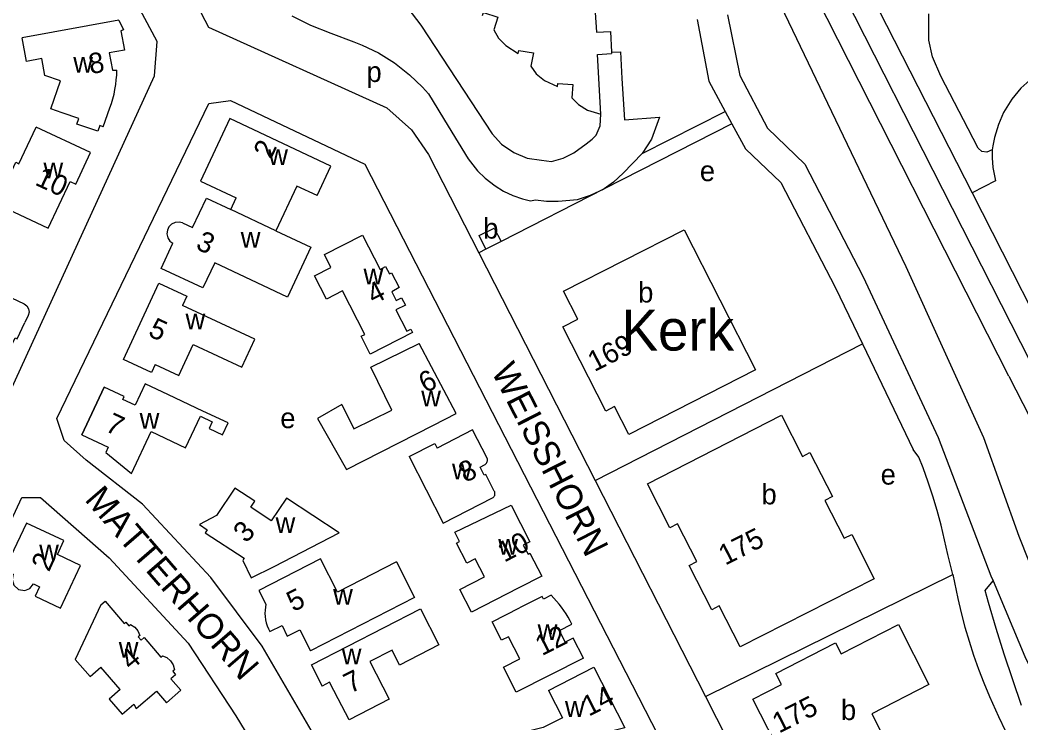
# Model space of a CAD drawing. Extents: x 158848 to 160613, y 385889 to 387762.
# Drawn here: x 159449.2 to 159645, y 386787.3 to 386924.8 of the extents above; entities that cross this region are included whole.
import ezdxf

# ---------------------------------------------------------------- set-up
doc = ezdxf.new("R2010")
doc.units = 0
for name, color, linetype in [('BLT_Basislijn', 7, 'Continuous'), ('BLT_Bebouwing', 7, 'Continuous'), ('BLT_Bebouwing_beschrifting', 7, 'Continuous'), ('BLT_Centroide', 7, 'Continuous'), ('BLT_Huisnummer', 7, 'Continuous'), ('BLT_Huisnummer_reeks', 7, 'Continuous'), ('BLT_Onderverdeling_panden', 7, 'Continuous'), ('BLT_Straatnaam', 7, 'Continuous')]:
    doc.layers.add(name, color=color, linetype=linetype)

msp = doc.modelspace()

# ---------------------------------------------------------------- linework, layer by layer
at = {"layer": 'BLT_Basislijn'}
for p, q in [((159642.66, 386855.15), (159599.65, 386939.76)), ((159593.58, 386936.96), (159622.47, 386876.62)), ((159648.81, 386854.1), (159607.24, 386935.86)), ((159626.97, 386920.9), (159627, 386926.08)), ((159627.69, 386917.65), (159626.97, 386920.9)), ((159629.31, 386913.82), (159627.69, 386917.65)), ((159634.66, 386903.55), (159629.31, 386913.82)), ((159647.35, 386913.56), (159645.02, 386911.51)), ((159645.02, 386911.51), (159643.23, 386909.32)), ((159486.14, 386908.53), (159490.34, 386909.11)), ((159643.23, 386909.32), (159641.6, 386906.73)), ((159456.36, 386846.86), (159486.14, 386908.53)), ((159641.6, 386906.73), (159640.59, 386904.4)), ((159588.47, 386904.54), (159563.46, 386891.77)), ((159636.63, 386899.79), (159634.66, 386903.55)), ((159640.59, 386904.4), (159639.84, 386901.84)), ((159639.84, 386901.84), (159639.54, 386900.23)), ((159637.38, 386899.14), (159636.63, 386899.79)), ((159638.32, 386898.99), (159637.38, 386899.14)), ((159639.39, 386899.44), (159638.32, 386898.99)), ((159639.54, 386900.23), (159639.39, 386899.44)), ((159602.75, 386896.61), (159614.14, 386874.61)), ((159563.46, 386891.77), (159543.28, 386881.47)), ((159540.34, 386879.98), (159538.94, 386879.26)), ((159608.68, 386872.59), (159614.01, 386861.47)), ((159561.67, 386834.72), (159614.01, 386861.47)), ((159614.01, 386861.47), (159623.91, 386840.81)), ((159642.66, 386855.15), (159675.21, 386790.95)), ((159457.8, 386842.55), (159456.36, 386846.86)), ((159462.11, 386838.72), (159457.8, 386842.55)), ((159625.04, 386839.31), (159623.91, 386840.81)), ((159473.11, 386830.1), (159462.11, 386838.72)), ((159486.51, 386815.74), (159473.11, 386830.1)), ((159496.56, 386802.33), (159486.51, 386815.74)), ((159583.26, 386792.43), (159631.71, 386816.34)), ((159637.99, 386813.18), (159639.56, 386815.1)), ((159506.61, 386785.09), (159496.56, 386802.33)), ((159640.63, 386788.54), (159647.72, 386773.62))]:
    msp.add_line(p, q, dxfattribs=at)
for points in [[(159378.73, 386868.21), (159381.51, 386870.25), (159384.89, 386871.94), (159390.8, 386873.2), (159397.02, 386873.2), (159403.72, 386871.28), (159415.21, 386866.02), (159440.57, 386853.09), (159443.92, 386851.65), (159447.27, 386852.13), (159475.51, 386913.9), (159475.98, 386920.61), (159471.2, 386929.7), (159460.12, 386951.5)], [(159608.45, 386947.37), (159609.58, 386941.77), (159635.45, 386891)], [(159477.85, 386939.23), (159486.03, 386923.44), (159520.96, 386907.65), (159525.75, 386903.34), (159529.1, 386898.55), (159538.94, 386879.26)], [(159521.87, 386931.43), (159527.59, 386923.85), (159534.57, 386913.21), (159541.55, 386902.57), (159543.39, 386900.57), (159545.82, 386898.92), (159548.42, 386897.8), (159551.21, 386897.38), (159553.18, 386897.16), (159555.46, 386897.79), (159557.56, 386898.84), (159559.96, 386900.64), (159561.1, 386901.53), (159561.87, 386902.29), (159562.32, 386903.21), (159562.68, 386904.14), (159562.79, 386906.39)], [(159502.36, 386925.67), (159506.01, 386923.84), (159509.95, 386922.24), (159514.48, 386920.6), (159516.12, 386919.94), (159519.28, 386918.42), (159522.42, 386916.43), (159525.4, 386914.09), (159527.91, 386911.7), (159529.07, 386910.41), (159532.95, 386904.05), (159536.84, 386897.7), (159538.71, 386895.33), (159540.19, 386893.9), (159542.13, 386892.36), (159543.76, 386891.36), (159545.62, 386890.49), (159547.46, 386889.83), (159549.06, 386889.45), (159550.02, 386889.66), (159552.2, 386889.42), (159554.48, 386889.36), (159558.26, 386889.73), (159560.76, 386890.56), (159563.46, 386891.77)], [(159581.66, 386924.93), (159583.96, 386912.85), (159587.17, 386906.95)], [(159587.6, 386925.88), (159589.99, 386914), (159595.45, 386903.65), (159602.75, 386896.61)], [(159564.9, 386918.55), (159566.64, 386918.63), (159566.95, 386913.37)], [(159566.95, 386913.37), (159567.43, 386905.31), (159574.28, 386905.8), (159572.75, 386901.5), (159570.91, 386898.7)], [(159490.34, 386909.11), (159516.66, 386896.66), (159588.92, 386755.88)], [(159570.91, 386898.7), (159587.17, 386906.95)], [(159587.17, 386906.95), (159588.47, 386904.54)], [(159588.47, 386904.54), (159591.14, 386899.62), (159598.04, 386893.01), (159608.68, 386872.59)], [(159639.39, 386899.44), (159639.35, 386897.88), (159639.52, 386896), (159640.02, 386893.39), (159635.45, 386891)], [(159570.91, 386898.7), (159567.18, 386894.84), (159565.29, 386893.1), (159563.46, 386891.77)], [(159635.45, 386891), (159655, 386852.65)], [(159538.94, 386879.26), (159561.67, 386834.72)], [(159622.47, 386876.62), (159637.71, 386843.11), (159644.61, 386823.85), (159651.79, 386805.73), (159658.98, 386790.78)], [(159614.14, 386874.61), (159628.8, 386843.11), (159639.15, 386816.08), (159639.56, 386815.1)], [(159631.71, 386816.34), (159630.69, 386820.27), (159630.08, 386823.14), (159629.39, 386825.99), (159628.62, 386828.83), (159627.78, 386831.64), (159626.86, 386834.42), (159625.87, 386837.18), (159625.04, 386839.31)], [(159561.67, 386834.72), (159583.26, 386792.43)], [(159449.52, 386831.37), (159453.18, 386831.37), (159466.59, 386819.58), (159482.04, 386802.91), (159491.39, 386788.68), (159497.08, 386779.33), (159500.74, 386768.76), (159508.06, 386749.25), (159509.27, 386740.71), (159510.09, 386736.65), (159507.24, 386735.84), (159449.92, 386721.2), (159447.48, 386722.01), (159425.13, 386772.02), (159423.91, 386775.67), (159425.13, 386778.93), (159449.52, 386831.37)], [(159631.71, 386816.34), (159632.66, 386811.64), (159633.32, 386808.83), (159634.05, 386806.05), (159634.85, 386803.28), (159635.74, 386800.53), (159636.69, 386797.81), (159637.73, 386795.12), (159638.84, 386792.46), (159640.02, 386789.83), (159640.63, 386788.54)], [(159639.56, 386815.1), (159645.76, 386800.27), (159650.93, 386789.63)], [(159645.15, 386790.69), (159643.41, 386795.69), (159641.75, 386800.72), (159640.17, 386805.77), (159638.66, 386810.85), (159637.99, 386813.18)], [(159583.26, 386792.43), (159600.4, 386758.82), (159625.25, 386766.9)]]:
    msp.add_lwpolyline(points, dxfattribs=at)
at = {"layer": 'BLT_Bebouwing'}
for p, q in [((159485.63, 386889.98), (159490.39, 386887.75)), ((159490.39, 386887.75), (159491.45, 386890.02)), ((159555.53, 386871.75), (159579.12, 386883.79)), ((159579.12, 386883.79), (159593.1, 386856.36)), ((159543.28, 386881.47), (159540.34, 386879.98)), ((159558.33, 386866.27), (159555.53, 386871.75)), ((159555.4, 386864.79), (159558.33, 386866.27)), ((159563.81, 386848.32), (159555.4, 386864.79)), ((159593.1, 386856.36), (159568.29, 386843.72)), ((159565.5, 386849.19), (159563.81, 386848.32)), ((159568.29, 386843.72), (159565.5, 386849.19))]:
    msp.add_line(p, q, dxfattribs=at)
for points in [[(159539.66, 386925.74), (159539.86, 386926.3), (159542.65, 386925.42), (159541.85, 386922.93), (159542.76, 386921.31), (159544.21, 386919.83), (159546.62, 386918.3)], [(159561.71, 386926.31), (159561.93, 386922.45), (159564.68, 386922.59)], [(159468.53, 386924.81), (159449.59, 386921.34)], [(159468.53, 386924.81), (159469.41, 386922.92), (159468.92, 386922.73)], [(159468.92, 386922.73), (159469.58, 386918.96), (159466.6, 386918.39), (159467.25, 386915.01), (159468.1, 386915.01)], [(159564.68, 386922.59), (159564.9, 386918.55)], [(159457.44, 386906.67), (159455.17, 386907.46), (159457.08, 386912.95), (159454.04, 386913.97), (159453.43, 386917.3), (159450.43, 386916.75), (159449.59, 386921.34)], [(159546.62, 386918.3), (159546.76, 386918.89)], [(159546.76, 386918.89), (159549.61, 386918.4), (159549.1, 386915.82), (159550.19, 386914.3), (159551.81, 386913.03), (159554.32, 386911.86)], [(159564.9, 386918.55), (159564.91, 386918.28)], [(159562.79, 386906.39), (159562.17, 386918.09), (159564.91, 386918.28)], [(159465.45, 386903.93), (159466.75, 386907.63), (159467.06, 386908.52), (159467.33, 386909.42), (159467.56, 386910.34), (159467.75, 386911.26), (159467.9, 386912.2), (159468.01, 386913.13), (159468.08, 386914.07), (159468.1, 386915.01)], [(159554.32, 386911.86), (159554.37, 386912.44)], [(159554.37, 386912.44), (159557.34, 386912.25), (159557.15, 386909.63), (159558.42, 386908.28), (159560.21, 386907.2), (159562.79, 386906.39)], [(159465.45, 386903.93), (159464.77, 386904.18), (159464.39, 386903.06), (159460.3, 386904.47), (159460.68, 386905.57), (159457.44, 386906.67)], [(159507.29, 386890.48), (159510, 386896.23), (159490.21, 386905.54), (159484.47, 386893.3), (159491.45, 386890.02)], [(159444.53, 386888.85), (159454.69, 386884.08), (159458.97, 386893.24), (159460.11, 386892.7), (159462.96, 386898.88), (159452.32, 386903.88)], [(159444.53, 386888.85), (159448.36, 386897), (159448.96, 386896.72), (159452.32, 386903.88)], [(159507.29, 386890.48), (159503.31, 386892.35), (159499.21, 386883.6)], [(159480.99, 386885.14), (159482.93, 386884.21), (159485.63, 386889.98)], [(159480.99, 386885.14), (159480.3, 386885.31), (159479.53, 386885.23), (159478.82, 386884.89), (159478.3, 386884.36), (159478, 386883.73), (159477.91, 386882.99), (159478.08, 386882.23), (159478.51, 386881.58), (159479.07, 386881.15)], [(159499.21, 386883.6), (159506.06, 386880.37), (159501.49, 386870.61)], [(159540.34, 386879.98), (159538.99, 386882.64), (159541.92, 386884.13), (159543.28, 386881.47)], [(159476.76, 386876.18), (159479.08, 386881.15)], [(159508.71, 386878.93), (159516.19, 386882.75), (159519.64, 386876.01), (159520.71, 386876.57), (159521.43, 386875.18), (159521.88, 386875.39), (159523.38, 386872.47), (159521.9, 386871.62), (159522.76, 386869.92), (159523.83, 386870.49), (159524.58, 386869.06), (159522.69, 386868.09), (159524.82, 386863.94), (159525.65, 386864.34), (159525.96, 386863.7), (159517.68, 386859.47)], [(159435.05, 386868.82), (159436.17, 386871.22), (159436.38, 386871.12), (159440.76, 386880.35), (159447.54, 386877.14), (159444.93, 386871.63), (159449.96, 386869.27), (159450.49, 386868.88), (159450.83, 386868.31), (159450.93, 386867.67), (159450.77, 386867.01), (159450.14, 386865.66)], [(159501.49, 386870.61), (159487.26, 386877.32), (159484.96, 386872.44), (159476.76, 386876.18)], [(159517.68, 386859.47), (159515.89, 386862.95), (159516.62, 386863.32), (159512.25, 386871.84), (159509.13, 386870.24), (159506.81, 386874.78), (159510, 386876.42), (159508.71, 386878.93)], [(159475.63, 386857.44), (159474.89, 386855.85), (159469.4, 386858.42), (159476.33, 386873.36), (159480.86, 386871.24)], [(159480.86, 386871.24), (159481.82, 386870.78), (159480.97, 386868.97)], [(159435.05, 386868.82), (159432.94, 386864.29), (159437.53, 386862.15), (159437.1, 386861.22), (159445.64, 386857.25), (159448.19, 386862.66), (159448.64, 386862.45), (159450.14, 386865.66)], [(159475.63, 386857.44), (159480.26, 386855.29), (159483.07, 386861.33), (159492.54, 386856.92), (159495.09, 386862.4), (159480.97, 386868.97)], [(159521.91, 386848.49), (159517.79, 386856.88), (159527.29, 386861.55)], [(159530.04, 386845.55), (159534.49, 386847.83), (159527.29, 386861.55)], [(159478.19, 386851.51), (159473.67, 386853.64), (159471.69, 386849.45), (159469.3, 386850.55), (159469.56, 386851.16), (159465.65, 386852.98), (159461.25, 386843.68), (159466.42, 386841.25), (159465.93, 386840.22)], [(159461.25, 386843.68), (159465.65, 386852.98)], [(159470.97, 386836.07), (159474.83, 386844.29), (159481.57, 386841.12), (159484.46, 386847.28), (159486.78, 386846.19), (159486.15, 386844.87), (159488.76, 386843.64), (159489.88, 386846), (159484.95, 386848.32), (159478.19, 386851.51)], [(159512.16, 386849.58), (159507.35, 386846.83), (159513.06, 386836.86), (159530.04, 386845.55)], [(159512.16, 386849.58), (159514.49, 386844.84), (159521.91, 386848.49)], [(159540.57, 386839.06), (159537.73, 386844.61), (159530.78, 386841.07)], [(159525.32, 386839.42), (159530.33, 386841.96), (159530.78, 386841.07)], [(159465.93, 386840.22), (159470.97, 386836.07)], [(159525.32, 386839.42), (159531.98, 386826.38), (159541.59, 386831.3)], [(159540.03, 386837.78), (159540.19, 386837.87), (159540.32, 386837.97), (159540.43, 386838.1), (159540.53, 386838.24), (159540.59, 386838.41), (159540.63, 386838.58), (159540.64, 386838.75), (159540.61, 386838.91), (159540.57, 386839.06)], [(159541.97, 386832.66), (159540.31, 386835.92), (159540.01, 386835.77), (159539.19, 386837.35), (159540.03, 386837.78)], [(159491.18, 386833.25), (159487.63, 386827.87), (159484.27, 386826.09)], [(159511.62, 386824.48), (159501.28, 386831.29), (159498.33, 386826.82), (159494.3, 386829.48), (159495.09, 386830.68), (159491.18, 386833.25)], [(159541.59, 386831.3), (159541.73, 386831.39), (159541.85, 386831.51), (159541.96, 386831.65), (159542.04, 386831.81), (159542.08, 386831.99), (159542.1, 386832.17), (159542.08, 386832.35), (159542.04, 386832.51), (159541.97, 386832.66)], [(159534.23, 386824.63), (159545.24, 386829.92), (159548.89, 386822.73), (159547.63, 386822.09), (159548.56, 386820.29), (159548.94, 386820.49), (159551.24, 386816.03), (159546.79, 386813.74)], [(159457.07, 386809.73), (159461.02, 386818.09), (159456.49, 386820.22), (159457.76, 386822.98), (159450.43, 386826.4), (159446.09, 386817.2), (159447.84, 386816.38), (159447.61, 386815.36), (159447.95, 386814.23), (159448.88, 386813.4), (159450.09, 386813.21), (159451.1, 386813.6), (159451.81, 386814.51), (159453.01, 386813.94), (159452.13, 386812.06), (159457.07, 386809.73)], [(159484.27, 386826.09), (159485.79, 386825.09), (159485.39, 386824.47), (159493.03, 386819.52), (159492.74, 386819.04), (159494.41, 386815.69), (159498.88, 386817.92)], [(159498.88, 386817.92), (159511.62, 386824.48)], [(159535.21, 386813.38), (159540.04, 386815.84), (159538.23, 386819.39), (159536.59, 386818.55), (159534.59, 386822.48), (159535.17, 386822.78), (159534.23, 386824.63)], [(159507.94, 386819.4), (159495.92, 386813.19), (159497.28, 386810.55)], [(159522.84, 386818.78), (159526.33, 386811.8), (159505.98, 386801.41)], [(159522.84, 386818.78), (159511.27, 386812.87), (159507.94, 386819.4)], [(159546.79, 386813.74), (159537.48, 386808.96), (159535.21, 386813.38)], [(159464.98, 386810.41), (159465.83, 386811.13), (159469.54, 386806.74), (159469.85, 386806.99), (159470.45, 386806.28), (159470.8, 386806.56), (159471.62, 386806.04), (159472.24, 386805.32), (159472.63, 386804.42), (159472.31, 386804.12), (159472.85, 386803.47), (159473.47, 386804.01)], [(159553.08, 386812.29), (159551.61, 386811.53), (159551.36, 386812.02), (159546.9, 386809.78)], [(159557.15, 386806.58), (159556.79, 386807.27), (159556.4, 386807.95), (159556, 386808.62), (159555.56, 386809.27), (159555.11, 386809.91), (159554.63, 386810.53), (159554.14, 386811.13), (159553.62, 386811.72), (159553.08, 386812.29)], [(159464.98, 386810.41), (159459.98, 386799.71), (159462.86, 386796.34), (159464.99, 386798.17)], [(159497.28, 386810.55), (159497.17, 386809.95), (159497.11, 386809.34), (159497.09, 386808.72), (159497.13, 386808.09), (159497.22, 386807.47), (159497.35, 386806.86), (159497.54, 386806.27), (159497.77, 386805.7), (159498.04, 386805.15)], [(159521.39, 386791.91), (159513.55, 386787.88), (159511.41, 386792.01), (159509.73, 386795.23), (159508.3, 386794.5), (159506.17, 386798.65), (159527.53, 386809.61)], [(159527.53, 386809.61), (159531.13, 386802.54), (159523.44, 386798.61), (159521.97, 386801.5), (159517.62, 386799.28), (159521.39, 386791.91)], [(159541.52, 386807.08), (159546.9, 386809.78)], [(159546.27, 386793.27), (159543.75, 386798.16), (159546.96, 386799.82), (159544.72, 386804.14), (159543.39, 386803.46), (159541.52, 386807.08)], [(159498.04, 386805.15), (159500.43, 386806.34), (159501.45, 386804.29), (159503.89, 386805.51), (159505.98, 386801.41)], [(159559.39, 386799.96), (159557.39, 386803.88), (159555.86, 386803.08), (159554.71, 386805.34), (159557.15, 386806.58)], [(159592.58, 386791.95), (159598.18, 386794.82), (159597.07, 386796.96), (159608.74, 386802.93), (159609.83, 386800.8), (159621.04, 386806.53), (159627.02, 386794.82), (159615.83, 386789.09), (159620.35, 386780.19), (159608.68, 386774.21), (159604.15, 386783.13), (159598.49, 386780.33), (159592.58, 386791.95)], [(159473.47, 386804.01), (159476.7, 386800.16), (159477.02, 386800.44), (159477.91, 386800.05), (159478.64, 386799.43), (159479.13, 386798.63), (159479.38, 386797.68), (159479.06, 386797.38), (159479.61, 386796.72), (159478.68, 386795.93), (159480.62, 386793.66), (159477.8, 386791.24)], [(159559.39, 386799.96), (159546.27, 386793.27)], [(159468.74, 386793.79), (159464.99, 386798.17)], [(159506.17, 386798.65), (159508.3, 386794.5)], [(159552.59, 386793.65), (159561.42, 386798.18), (159567.48, 386786.35), (159562.82, 386785.14), (159563.69, 386781.79), (159558.85, 386780.54)], [(159468.74, 386793.79), (159466.61, 386791.96), (159469.15, 386788.99), (159471.43, 386790.95), (159471.88, 386790.12), (159475.85, 386793.52), (159477.8, 386791.24)], [(159552.59, 386793.65), (159555.32, 386788.3), (159551.53, 386786.38), (159546.11, 386784.99), (159547.71, 386778.76)]]:
    msp.add_lwpolyline(points, dxfattribs=at)
msp.add_lwpolyline([(159571.93, 386834.1), (159598.16, 386847.49), (159602.25, 386839.43), (159603.72, 386840.2), (159608.14, 386831.56), (159606.66, 386830.8), (159610.43, 386823.42), (159611.91, 386824.17), (159616.31, 386815.51), (159590.08, 386802.15), (159585.99, 386810.18), (159584.5, 386809.43), (159580.09, 386818.08), (159581.57, 386818.84), (159577.81, 386826.22), (159576.33, 386825.46)], close=True, dxfattribs=at)
at = {"layer": 'BLT_Onderverdeling_panden'}
msp.add_line((159499.21, 386883.6), (159490.39, 386887.75), dxfattribs=at)

# ---------------------------------------------------------------- texts
at = {"layer": 'BLT_Bebouwing_beschrifting'}
msp.add_text('Kerk', height=8, dxfattribs=at).set_placement((159566.87, 386860.16))
at = {"layer": 'BLT_Centroide'}
for s, p in [('w', (159459.58, 386914.55)), ('p', (159516.96, 386912.71)), ('w', (159497.73, 386896.47)), ('w', (159453.75, 386893.88)), ('e', (159582.19, 386893.31)), ('b', (159539.8, 386882.06)), ('w', (159492.35, 386880.28)), ('w', (159516.38, 386873.08)), ('b', (159570.12, 386869.55)), ('w', (159481.55, 386864.31)), ('w', (159527.66, 386849.22)), ('w', (159472.57, 386844.84)), ('e', (159500.09, 386844.96)), ('w', (159533.7, 386834.92)), ('e', (159617.56, 386833.92)), ('b', (159594.25, 386830.05)), ('w', (159499.17, 386824.47)), ('w', (159542.73, 386820.19)), ('w', (159452.91, 386819.12)), ('w', (159510.43, 386810.41)), ('w', (159550.45, 386803.48)), ('w', (159468.48, 386800.06)), ('w', (159512.12, 386798.75)), ('w', (159555.8, 386788.47)), ('b', (159609.8, 386787.83))]:
    msp.add_text(s, height=4, dxfattribs=at).set_placement(p)
at = {"layer": 'BLT_Huisnummer'}
for s, rotation, p in [('8', 9.9027, (159462.97, 386914.24)), ('2', 64.8544, (159498.27, 386897.43)), ('10', 334.9368, (159451.9, 386892.67)), ('3', 334.9187, (159483.34, 386880.15)), ('4', 27.0411, (159518.34, 386869.11)), ('5', 334.8936, (159474.03, 386863.12)), ('169', 27.0403, (159561.55, 386855.92)), ('6', 27.0411, (159528.48, 386851.76)), ('7', 334.8981, (159465.62, 386844.51)), ('8', 27.0411, (159536.29, 386834.21)), ('3', 46.0814, (159493.37, 386822.32)), ('10', 27.0433, (159543.9, 386818.63)), ('175', 27.0746, (159587.15, 386818.03)), ('2', 65.6001, (159454.83, 386816.69)), ('5', 27.0481, (159502.65, 386808.94)), ('12', 27.04, (159551.29, 386800.33)), ('4', 39.3489, (159470.83, 386797.44)), ('7', 27.0481, (159513.81, 386792.96)), ('14', 27.0028, (159560.46, 386788.47))]:
    msp.add_text(s, height=4, rotation=rotation, dxfattribs=at).set_placement(p)
at = {"layer": 'BLT_Huisnummer_reeks'}
msp.add_text('175', height=4, rotation=27.0746, dxfattribs=at).set_placement((159597.68, 386785.17))
at = {"layer": 'BLT_Straatnaam'}
for s, rotation, p in [('WEISSHORN', 297.0407, (159541.28, 386856.15)), ('MATTERHORN', 310.8906, (159461.64, 386830.92))]:
    msp.add_text(s, height=5, rotation=rotation, dxfattribs=at).set_placement(p)

doc.saveas('drawing.dxf')
